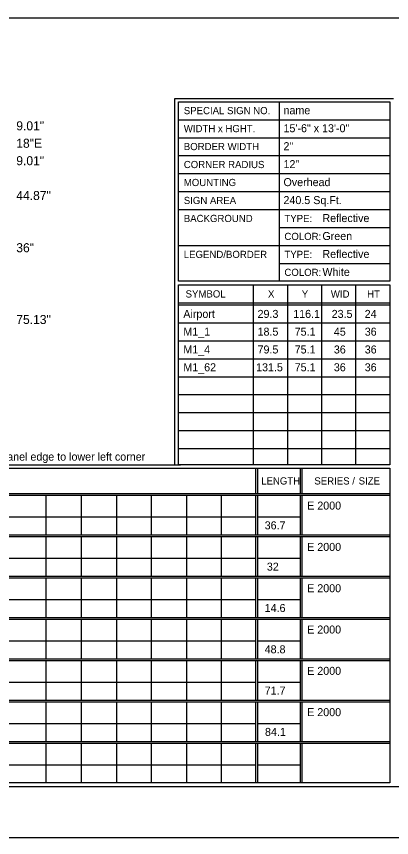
# Model space of a CAD drawing. Extents: x 2149934 to 2150188, y 145113 to 145238.
# Drawn here: x 2150052 to 2150076.2, y 145114.1 to 145167.1 of the extents above; entities that cross this region are included whole.
import ezdxf

# ---------------------------------------------------------------- set-up
doc = ezdxf.new("R2010")
doc.units = 0
for name, color, linetype in [('BORDER', 7, 'Continuous'), ('GSDIMS', 7, 'Continuous'), ('GSSHT', 7, 'Continuous'), ('Level 1', 7, 'Continuous'), ('PDF', 7, 'Continuous')]:
    doc.layers.add(name, color=color, linetype=linetype)

msp = doc.modelspace()

# ---------------------------------------------------------------- linework, layer by layer
at = {"layer": 'BORDER'}
for p, q in [((2150017.557, 145117.388), (2150171.536, 145117.388)), ((2150010.458, 145114.088), (2150174.061, 145114.088))]:
    msp.add_line(p, q, dxfattribs=at)
at = {"layer": 'Level 1'}
for p, q in [((2150135.447, 145166.95), (2150017.557, 145166.95)), ((2150062.21, 145161.778), (2150076.316, 145161.778)), ((2150068.935, 145161.546), (2150068.935, 145149.975)), ((2150062.442, 145160.387), (2150076.084, 145160.387)), ((2150062.442, 145159.227), (2150076.084, 145159.227)), ((2150062.442, 145158.091), (2150076.084, 145158.091)), ((2150062.442, 145156.932), (2150076.084, 145156.932)), ((2150062.442, 145155.772), (2150076.084, 145155.772)), ((2150062.442, 145154.613), (2150076.084, 145154.613)), ((2150068.935, 145153.453), (2150076.084, 145153.453)), ((2150062.442, 145152.294), (2150076.084, 145152.294)), ((2150068.935, 145151.134), (2150076.084, 145151.134)), ((2150062.442, 145138.143), (2150062.442, 145149.743)), ((2150062.442, 145149.743), (2150076.084, 145149.743)), ((2150067.272, 145149.737), (2150067.272, 145148.578)), ((2150069.475, 145149.737), (2150069.475, 145148.578)), ((2150071.678, 145149.737), (2150071.678, 145148.578)), ((2150073.881, 145149.737), (2150073.881, 145148.578)), ((2150076.084, 145149.743), (2150076.084, 145138.143)), ((2150062.442, 145148.578), (2150076.084, 145148.578)), ((2150062.442, 145148.462), (2150076.084, 145148.462)), ((2150067.272, 145148.578), (2150067.272, 145138.143)), ((2150069.475, 145148.578), (2150069.475, 145138.143)), ((2150071.678, 145148.578), (2150071.678, 145138.143)), ((2150073.881, 145148.578), (2150073.881, 145138.143)), ((2150062.442, 145147.303), (2150076.084, 145147.303)), ((2150062.442, 145146.143), (2150076.084, 145146.143)), ((2150062.442, 145144.984), (2150076.084, 145144.984)), ((2150062.442, 145143.824), (2150076.084, 145143.824)), ((2150062.442, 145142.665), (2150076.084, 145142.665)), ((2150062.442, 145141.505), (2150076.084, 145141.505)), ((2150062.442, 145140.346), (2150076.084, 145140.346)), ((2150062.442, 145139.186), (2150076.084, 145139.186)), ((2150017.557, 145138.143), (2150062.583, 145138.143)), ((2150076.084, 145138.143), (2150062.442, 145138.143)), ((2150067.426, 145137.911), (2150067.426, 145136.288)), ((2150067.542, 145137.911), (2150067.542, 145136.288)), ((2150070.29, 145137.911), (2150070.29, 145136.288)), ((2150070.405, 145137.911), (2150070.405, 145136.288)), ((2150017.789, 145136.288), (2150076.084, 145136.288)), ((2150017.789, 145136.172), (2150076.084, 145136.172)), ((2150053.895, 145136.172), (2150053.895, 145133.621)), ((2150056.168, 145136.172), (2150056.168, 145133.621)), ((2150058.441, 145136.172), (2150058.441, 145133.621)), ((2150060.69, 145136.172), (2150060.69, 145133.621)), ((2150062.962, 145136.172), (2150062.962, 145133.621)), ((2150065.212, 145136.172), (2150065.212, 145133.621)), ((2150067.426, 145136.172), (2150067.426, 145133.621)), ((2150067.542, 145136.172), (2150067.542, 145133.621)), ((2150070.29, 145136.172), (2150070.29, 145133.621)), ((2150070.405, 145136.172), (2150070.405, 145133.621)), ((2150017.789, 145134.78), (2150067.426, 145134.78)), ((2150067.542, 145134.78), (2150070.29, 145134.78)), ((2150017.789, 145133.621), (2150076.084, 145133.621)), ((2150017.789, 145133.505), (2150076.084, 145133.505)), ((2150053.895, 145133.505), (2150053.895, 145130.954)), ((2150056.168, 145133.505), (2150056.168, 145130.954)), ((2150058.441, 145133.505), (2150058.441, 145130.954)), ((2150060.69, 145133.505), (2150060.69, 145130.954)), ((2150062.962, 145133.505), (2150062.962, 145130.954)), ((2150065.212, 145133.505), (2150065.212, 145130.954)), ((2150067.426, 145133.505), (2150067.426, 145130.954)), ((2150067.542, 145133.505), (2150067.542, 145130.954)), ((2150070.29, 145133.505), (2150070.29, 145130.954)), ((2150070.405, 145133.505), (2150070.405, 145130.954)), ((2150017.789, 145132.113), (2150067.426, 145132.113)), ((2150067.542, 145132.113), (2150070.29, 145132.113)), ((2150017.789, 145130.954), (2150076.084, 145130.954)), ((2150017.789, 145130.838), (2150076.084, 145130.838)), ((2150053.895, 145130.838), (2150053.895, 145128.287)), ((2150056.168, 145130.838), (2150056.168, 145128.287)), ((2150058.441, 145130.838), (2150058.441, 145128.287)), ((2150060.69, 145130.838), (2150060.69, 145128.287)), ((2150062.962, 145130.838), (2150062.962, 145128.287)), ((2150065.212, 145130.838), (2150065.212, 145128.287)), ((2150067.426, 145130.838), (2150067.426, 145128.287)), ((2150067.542, 145130.838), (2150067.542, 145128.287)), ((2150070.29, 145130.838), (2150070.29, 145128.287)), ((2150070.405, 145130.838), (2150070.405, 145128.287)), ((2150017.789, 145129.447), (2150067.426, 145129.447)), ((2150067.542, 145129.447), (2150070.29, 145129.447)), ((2150017.789, 145128.287), (2150076.084, 145128.287)), ((2150017.789, 145128.171), (2150076.084, 145128.171)), ((2150053.895, 145128.171), (2150053.895, 145125.62)), ((2150056.168, 145128.171), (2150056.168, 145125.62)), ((2150058.441, 145128.171), (2150058.441, 145125.62)), ((2150060.69, 145128.171), (2150060.69, 145125.62)), ((2150062.962, 145128.171), (2150062.962, 145125.62)), ((2150065.212, 145128.171), (2150065.212, 145125.62)), ((2150067.426, 145128.171), (2150067.426, 145125.62)), ((2150067.542, 145128.171), (2150067.542, 145125.62)), ((2150070.29, 145128.171), (2150070.29, 145125.62)), ((2150070.405, 145128.171), (2150070.405, 145125.62)), ((2150017.789, 145126.78), (2150067.426, 145126.78)), ((2150067.542, 145126.78), (2150070.29, 145126.78)), ((2150017.789, 145125.62), (2150076.084, 145125.62)), ((2150017.789, 145125.504), (2150076.084, 145125.504)), ((2150053.895, 145125.504), (2150053.895, 145122.954)), ((2150056.168, 145125.504), (2150056.168, 145122.954)), ((2150058.441, 145125.504), (2150058.441, 145122.954)), ((2150060.69, 145125.504), (2150060.69, 145122.954)), ((2150062.962, 145125.504), (2150062.962, 145122.954)), ((2150065.212, 145125.504), (2150065.212, 145122.954)), ((2150067.426, 145125.504), (2150067.426, 145122.954)), ((2150067.542, 145125.504), (2150067.542, 145122.954)), ((2150070.29, 145125.504), (2150070.29, 145122.954)), ((2150070.405, 145125.504), (2150070.405, 145122.954)), ((2150017.789, 145124.113), (2150067.426, 145124.113)), ((2150067.542, 145124.113), (2150070.29, 145124.113)), ((2150017.789, 145122.954), (2150076.084, 145122.954)), ((2150017.789, 145122.838), (2150076.084, 145122.838)), ((2150053.895, 145122.838), (2150053.895, 145120.287)), ((2150056.168, 145122.838), (2150056.168, 145120.287)), ((2150058.441, 145122.838), (2150058.441, 145120.287)), ((2150060.69, 145122.838), (2150060.69, 145120.287)), ((2150062.962, 145122.838), (2150062.962, 145120.287)), ((2150065.212, 145122.838), (2150065.212, 145120.287)), ((2150067.426, 145122.838), (2150067.426, 145120.287)), ((2150067.542, 145122.838), (2150067.542, 145120.287)), ((2150070.29, 145122.838), (2150070.29, 145120.287)), ((2150070.405, 145122.838), (2150070.405, 145120.287)), ((2150017.789, 145121.446), (2150067.426, 145121.446)), ((2150067.542, 145121.446), (2150070.29, 145121.446)), ((2150017.789, 145120.287), (2150076.084, 145120.287)), ((2150017.789, 145120.171), (2150076.084, 145120.171)), ((2150053.895, 145120.171), (2150053.895, 145117.62)), ((2150056.168, 145120.171), (2150056.168, 145117.62)), ((2150058.441, 145120.171), (2150058.441, 145117.62)), ((2150060.69, 145120.171), (2150060.69, 145117.62)), ((2150062.962, 145120.171), (2150062.962, 145117.62)), ((2150065.212, 145120.171), (2150065.212, 145117.62)), ((2150067.426, 145120.171), (2150067.426, 145117.62)), ((2150067.542, 145120.171), (2150067.542, 145117.62)), ((2150070.29, 145120.171), (2150070.29, 145117.62)), ((2150070.405, 145120.171), (2150070.405, 145117.62)), ((2150017.789, 145118.779), (2150067.426, 145118.779)), ((2150067.542, 145118.779), (2150070.29, 145118.779))]:
    msp.add_line(p, q, dxfattribs=at)
msp.add_lwpolyline([(2150062.21, 145138.143), (2150062.21, 145161.778)], dxfattribs=at)
for points in [[(2150062.442, 145161.546), (2150076.084, 145161.546), (2150076.084, 145149.975), (2150062.442, 145149.975)], [(2150017.789, 145137.911), (2150076.084, 145137.911), (2150076.084, 145117.62), (2150017.789, 145117.62)]]:
    msp.add_lwpolyline(points, close=True, dxfattribs=at)
at = {"layer": 'PDF'}
msp.add_lwpolyline([(2150010.458, 145114.088), (2150174.061, 145114.088), (2150174.061, 145219.948), (2150010.458, 145219.948)], close=True, dxfattribs=at)

# ---------------------------------------------------------------- texts
at = {"layer": 'GSDIMS'}
for s, p in [('9.01"', (2150051.978, 145159.717)), ('18"E', (2150051.978, 145158.592)), ('9.01"', (2150051.978, 145157.466)), ('44.87"', (2150051.978, 145155.221)), ('36"', (2150051.978, 145151.852)), ('75.13"', (2150051.978, 145147.221))]:
    msp.add_text(s, height=0.5833, dxfattribs=at).set_placement(p)
at = {"layer": 'GSSHT'}
for s, p in [('name', (2150069.224, 145160.753)), ('Overhead', (2150069.224, 145156.117))]:
    msp.add_text(s, height=0.5165, dxfattribs=at).set_placement(p)
at = {"layer": 'Level 1'}
for s, height, p in [('SPECIAL SIGN NO.', 0.46374, (2150062.79, 145160.758)), ('WIDTH x HGHT.', 0.46374, (2150062.79, 145159.598)), ('15\'-6" x 13\'-0"', 0.51652, (2150069.224, 145159.594)), ('BORDER WIDTH', 0.46374, (2150062.79, 145158.439)), ('2"', 0.5165, (2150069.224, 145158.435)), ('CORNER RADIUS', 0.46374, (2150062.79, 145157.28)), ('12"', 0.5165, (2150069.224, 145157.276)), ('MOUNTING', 0.4637, (2150062.79, 145156.12)), ('SIGN AREA', 0.4638, (2150062.79, 145154.961)), ('240.5 Sq.Ft.', 0.51652, (2150069.224, 145154.958)), ('BACKGROUND', 0.4637, (2150062.79, 145153.801)), ('TYPE:', 0.4637, (2150069.283, 145153.801)), ('Reflective', 0.5165, (2150071.736, 145153.799)), ('COLOR:', 0.4637, (2150069.283, 145152.642)), ('Green', 0.5165, (2150071.736, 145152.64)), ('LEGEND/BORDER', 0.46374, (2150062.79, 145151.482)), ('TYPE:', 0.4637, (2150069.283, 145151.482)), ('Reflective', 0.5165, (2150071.736, 145151.482)), ('White', 0.5165, (2150071.736, 145150.323)), ('COLOR:', 0.4637, (2150069.283, 145150.323)), ('SYMBOL', 0.4637, (2150062.906, 145148.931)), ('X', 0.464, (2150068.223, 145148.926)), ('Y', 0.464, (2150070.403, 145148.926)), ('WID', 0.4637, (2150072.281, 145148.926)), ('HT', 0.4637, (2150074.623, 145148.926)), ('Airport', 0.5165, (2150062.761, 145147.615)), ('29.3', 0.5165, (2150067.551, 145147.615)), ('116.1', 0.5165, (2150069.851, 145147.615)), ('23.5', 0.5165, (2150072.333, 145147.615)), ('24', 0.5165, (2150074.464, 145147.615)), ('M1_1', 0.5165, (2150062.761, 145146.468)), ('18.5', 0.5165, (2150067.551, 145146.468)), ('75.1', 0.5165, (2150069.946, 145146.468)), ('45', 0.5165, (2150072.474, 145146.468)), ('36', 0.5165, (2150074.467, 145146.468)), ('M1_4', 0.5165, (2150062.761, 145145.32)), ('79.5', 0.5165, (2150067.551, 145145.32)), ('75.1', 0.5165, (2150069.946, 145145.32)), ('36', 0.5165, (2150072.474, 145145.32)), ('36', 0.5165, (2150074.467, 145145.32)), ('M1_62', 0.5165, (2150062.761, 145144.172)), ('131.5', 0.5165, (2150067.457, 145144.172)), ('75.1', 0.5165, (2150069.946, 145144.172)), ('36', 0.5165, (2150072.474, 145144.172)), ('36', 0.5165, (2150074.467, 145144.172)), ('Letter locations are panel edge to lower left corner', 0.51652, (2150044.943, 145138.406)), ('LENGTH', 0.4638, (2150067.783, 145136.867)), ('LENGTH', 0.4638, (2150067.783, 145136.867)), ('SERIES /', 0.4638, (2150071.216, 145136.867)), ('SIZE', 0.4638, (2150074.074, 145136.867)), ('E 2000', 0.5165, (2150070.753, 145135.248)), ('36.7', 0.5165, (2150068.009, 145133.973)), ('E 2000', 0.5165, (2150070.753, 145132.583)), ('32', 0.5165, (2150068.15, 145131.308)), ('E 2000', 0.5165, (2150070.753, 145129.917)), ('14.6', 0.5165, (2150068.009, 145128.642)), ('E 2000', 0.5165, (2150070.753, 145127.252)), ('48.8', 0.5165, (2150068.009, 145125.977)), ('E 2000', 0.5165, (2150070.753, 145124.586)), ('71.7', 0.5165, (2150068.009, 145123.311)), ('E 2000', 0.5165, (2150070.753, 145121.921)), ('84.1', 0.5165, (2150068.03, 145120.646))]:
    msp.add_text(s, height=height, dxfattribs=at).set_placement(p)

doc.saveas('drawing.dxf')
